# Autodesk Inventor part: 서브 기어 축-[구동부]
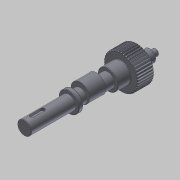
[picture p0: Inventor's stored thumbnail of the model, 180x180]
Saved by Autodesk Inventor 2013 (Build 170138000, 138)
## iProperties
Created: 2018-12
Part Number: 서브 기어 축-[구동부]
Material: 강철, 연강
Document SubType Name: Modeling
Designer: mduedu
Categories: <?xml version="1.0" encoding="UTF-16"?> <MemberInstance><Categories><FamilyTemplate><FamilyTemplateParameter ValueType="xs:double" Id="1" ObjectReferenceKey="da
Density: 7.86 g/cm^3
Mass: 514.749 g
Surface Area: 160.365 cm^2
Volume: 65.4897 cm^3
Author: mduedu
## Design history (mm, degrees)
sketch "Sketch1"
  geometry: C1 r 21.3 at (0, 0)
  constraints: 1 centre point
  dimensions: "d0" = 42.6 diameter of C1 (= da_da)
extrude "Extrusion1" new body sketch "Sketch1" distance "d1" = 20 (= da_b); taper "d2" = 0 deg
workplane "Work Plane2"
sketch "Sketch2"
  geometry: C1 r 21.3 at (0, 0) reference; C2 r 20.5 at (0, 0)
  constraints: 1 centre point, 1 coincident
  dimensions: "d3" = 41 diameter of C2 (= da_dw)
feature "피치 지름" sketch "Sketch2" dims "d4" = 10, "d5" = 0
workplane "Work Plane8"
workplane "Work Plane9"
chamfer "모따기1" distance "d49" = 1; stored, may be unused: second distance "d50" = 2, angle "d51" = 45 deg
sketch "스케치3"
  geometry: C1 r 12.5 at (0, 0); 1 further point
  constraints: 1 centre point, 1 coincident
  dimensions: "d52" = 25 diameter of C1
extrude "돌출2" join sketch "스케치3" distance "d53" = 16; taper "d54" = 0 deg
sketch "스케치4"
  geometry: C1 r 8.5 at (0, 0); 1 further point
  constraints: 1 centre point, 1 coincident
  dimensions: "d55" = 17 diameter of C1
extrude "돌출3" join sketch "스케치4" distance "d56" = 103; taper "d57" = 0 deg
sketch "스케치5"
  geometry: C1 r 7.5 at (0, 0); 1 further point
  constraints: 1 centre point, 1 coincident
  dimensions: "d58" = 15 diameter of C1
extrude "돌출4" join sketch "스케치5" distance "d59" = 16; taper "d60" = 0 deg
sketch "스케치6"
  geometry: C1 r 4 at (0, 0); 1 further point
  constraints: 1 centre point, 1 coincident
  dimensions: "d61" = 8 diameter of C1
extrude "돌출5" join sketch "스케치6" distance "d62" = 7; taper "d63" = 0 deg
chamfer "모따기2" distance "d64" = 0.5; stored, may be unused: second distance "d65" = 2, angle "d66" = 45 deg
fillet "모깎기1" dims "d67" = 0.5
feature "스퍼 기어" dims "da_b" = 20, "da_d" = 41, "da_aw" = 31, "da_da" = 42.6, "da_df" = 39.086, "da_dw" = 41, angle "da_beta" = 0 deg, "da_lefttooth" = 0, "da_righttooth" = 0
node "작업 평면11"
sketch "스케치7"
  geometry: C1 r 11.5 at (0, 3); C2 r 8.5 at (0, 0) reference; 1 further point
  constraints: 1 centre point, 1 tangent, 1 vertical alignment
  dimensions: "d69" = 3 distance of point (0, 0) C1.centre; "d70" = 23 diameter of C1 (derived)
extrude "돌출6" join sketch "스케치7" stored distance "d71" = 20; taper "d72" = 0 deg
node "작업 평면12"
sketch "스케치8"
  geometry: C1 r 12.5 at (0, 0) reference; C2 r 12.5 at (0, 0) reference; 1 further point
extrude "돌출7" join sketch "스케치8" distance "d74" = 5; taper "d75" = 0 deg
chamfer "모따기3" distance "d76" = 0.5; stored, may be unused: second distance "d77" = 2, angle "d78" = 45 deg
sketch "스케치9"
  geometry: L1 (-8, 139)-(8, 139) reference; L2 (0, 139)-(0, 0); L3 (-8.5, 84)-(-8.5, 138.5) reference; L4 (-8.5, 115)-(0, 115); L5 (-8.5, 115)-(-8.5, 113.5); L6 (-8.5, 113.5)-(-7, 115); L7 (-7, 115)-(-8.5, 115)
  constraints: 10 end point, 4 point on line, 2 perpendicular, 1 collinear, 1 midpoint
  dimensions: "d79" = 24 distance between parallel lines of L4 L1; "d80" = 3 diameter of L5.end L4; "d81" = 45 deg angle of L6 L3
revolve "회전1" sketch "스케치9" stored, may be unused: angle "d82" = 90 deg
sketch "스케치10"
  geometry: L1 (-8.5, 116.5)-(-7, 115) reference; L2 (-8.5, 113.5)-(-7, 115) reference; 2 further points
  constraints: 1 coincident
node "작업점1"
node "작업 평면13"
sketch "스케치11"
  geometry: L1 (-2.5, 93.5)-(-2.5, 80.5); L2 (2.5, 80.5)-(2.5, 93.5); L3 (-8, 103)-(8, 103) reference; A1 r 2.5 centre (0, 93.5) between (2.5, 93.5) and (-2.5, 93.5); A2 r 2.5 centre (0, 80.5) between (-2.5, 80.5) and (2.5, 80.5); 1 further point
  constraints: 4 end point, 4 point on circle, 4 tangent, 2 centre point, 2 vertical alignment, 1 parallel
  dimensions: "d83" = 7 distance edge to line of A1 L3; "d84" = 18 dimension on A2 A1; "d85" = 5 distance between parallel lines of L1 L2
extrude "돌출8" cut sketch "스케치11" distance "d86" = 3; taper "d87" = 0 deg
sketch "스케치12" dims "d88" = 32
  geometry: C1 r 0.5 at (0, -16); 2 further points
  constraints: 2 vertical alignment, 1 centre point, 1 coincident, 2 other
  dimensions: "d89" = 1 diameter of C1
extrude "돌출9" join sketch "스케치12" distance "d90" = 0.3; taper "d91" = 0 deg
sketch "스케치13"
  geometry: C1 r 11.5 at (0, 3) reference; 1 further point
  node "절단 모서리 투영1"
body "Solid1"
body "Srf1"
node "투영된 루프1"
other parameters: "d16" = 31 (= da_aw), "d17" = 0, "d34" = 0.76624 (computed from da_z), "d39" = 0, "d41" = 0, "d43" = 31 (= da_aw), "d46" = 31 (= da_aw), "d47" = 0, "d48" = 0, "d68" = 24, "d73" = 48
